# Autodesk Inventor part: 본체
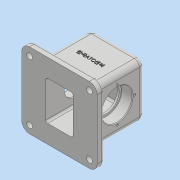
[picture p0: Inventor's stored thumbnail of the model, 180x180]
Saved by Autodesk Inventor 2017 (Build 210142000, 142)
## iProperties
Part Number: 본체
Material: 일반
Document SubType Name: Modeling
Designer: MRC
Density: 1 g/cm^3
Appearance: 기본값
Mass: 392.441 g
Surface Area: 723.029 cm^2
Volume: 392.441 cm^3
Author: MRC
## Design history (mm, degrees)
sketch "스케치1"
  geometry: L1 (-41, 41)-(41, 41); L2 (41, 41)-(41, -41); L3 (41, -41)-(-41, -41); L4 (-41, -41)-(-41, 41); L5 (-41, 41)-(41, -41); L6 (41, 41)-(-41, -41); 1 further point
  constraints: 12 end point, 2 midpoint, 2 parallel, 1 horizontal, 1 perpendicular
  dimensions: "d0" = 82 distance of L2.end L3.end; "d1" = 82 distance of L1.end L2.end
extrude "돌출1" new body sketch "스케치1" distance "d2" = 42; taper "d3" = 0 deg; dims "d67" = 38, "d68" = 0
sketch "스케치2"
  geometry: C1 r 23.5 at (-41, 38); 1 further point
  constraints: 1 centre point, 1 coincident
  dimensions: "d4" = 23.5 radius of C1
extrude "돌출2" cut sketch "스케치2" distance "d5" = 17; taper "d6" = 0 deg
sketch "스케치3"
  geometry: C1 r 20 at (0, 0); 1 further point
  constraints: 1 centre point, 1 coincident
  dimensions: "d7" = 20 radius of C1
extrude "돌출3" cut sketch "스케치3" distance "d8" = 3; taper "d9" = 0 deg
sketch "스케치4"
  geometry: 2 further points
  constraints: 1 vertical alignment
  dimensions: "d10" = 27 distance of point (-41, 38) point (-41, 65)
hole "구멍1" sketch "스케치4" at (-41, 65) diameter "d11" = 3.242; stored, may be unused: countersink angle "d15" = 90 deg, drill point angle "d17" = 118 deg; dims "d12" = 8, "d13" = 4, "d14" = 2, "d16" = 10
sketch "스케치6"
  geometry: L1 (-58, -58)-(58, -58); L2 (58, -58)-(58, 58); L3 (58, 58)-(-58, 58); L4 (-58, 58)-(-58, -58); L5 (-58, -58)-(58, 58); L6 (58, -58)-(-58, 58); 1 further point
  constraints: 12 end point, 2 midpoint, 2 parallel, 1 horizontal, 1 perpendicular
  dimensions: "d23" = 116 distance of L3.end L2.end; "d24" = 116 distance of L2.end L1.end
extrude "돌출4" join sketch "스케치6" distance "d25" = 10; taper "d26" = 0 deg
sketch "스케치7"
  geometry: L1 (21, -30)-(-21, -30); L2 (-21, -30)-(-21, 30); L3 (-21, 30)-(21, 30); L4 (21, 30)-(21, -30); L5 (21, -30)-(-21, 30); L6 (-21, -30)-(21, 30); 1 further point
  constraints: 12 end point, 2 midpoint, 2 parallel, 1 horizontal, 1 perpendicular
  dimensions: "d27" = 42 distance of L2.end L3.end; "d28" = 60 distance of L1.end L2.end
extrude "돌출5" cut sketch "스케치7" distance "d29" = 80; taper "d30" = 0 deg
sketch "스케치8"
  geometry: C1 r 7.5 at (0, 0); 1 further point
  constraints: 1 centre point, 1 coincident
  dimensions: "d31" = 7.5 radius of C1
extrude "돌출6" join sketch "스케치8" distance "d32" = 4; taper "d33" = 0 deg
sketch "스케치9"
  geometry: 1 further point
hole "구멍2" sketch "스케치9" at (0, 0) diameter "d34" = 4.917; stored, may be unused: countersink angle "d38" = 90 deg, drill point angle "d40" = 118 deg; dims "d35" = 20, "d36" = 4, "d37" = 2, "d39" = 17.1
fillet "모깎기1" dims "d41" = 8
fillet "모깎기2" dims "d42" = 8
fillet "모깎기3" dims "d43" = 3
fillet "모깎기4" dims "d44" = 12
fillet "모깎기5" dims "d45" = 3
fillet "모깎기6" dims "d46" = 3
sketch "스케치10"
  geometry: C1 r 4.5 at (-46, 46); A1 r 12 centre (-46, 46) between (-46, 58) and (-58, 46) reference; 1 further point
  constraints: 1 centre point, 1 coincident
  dimensions: "d47" = 4.5 radius of C1
extrude "돌출7" cut sketch "스케치10" stored distance "d48" = 4; taper "d49" = 0 deg
chamfer "모따기1" distance "d50" = 1; stored, may be unused: second distance "d51" = 2, angle "d52" = 45 deg
chamfer "모따기2" distance "d53" = 1; stored, may be unused: second distance "d54" = 2, angle "d55" = 45 deg
fillet "모깎기7" dims "d62" = 3
fillet "모깎기8" dims "d63" = 3
sketch "스케치11"
  geometry: L1 (79, -82)-(-13, -82) reference; 2 further points
  constraints: 1 coincident, 1 other
  dimensions: "d64" = 48 distance from line of L1 point (33, -34)
feature "엠보싱1" sketch "스케치11" dims "d0" = 82, "d1" = 82, "d13" = 4, "d65" = 0.5, "d66" = 0
fillet "모깎기9" dims "d69" = 0.6
fillet "모깎기10" dims "d70" = 0.6
node "솔리드1"
pattern_circular "원형 패턴1" dims angle "d19" = 360 deg
mirror "미러1"
mirror "미러2"
mirror "미러3"
